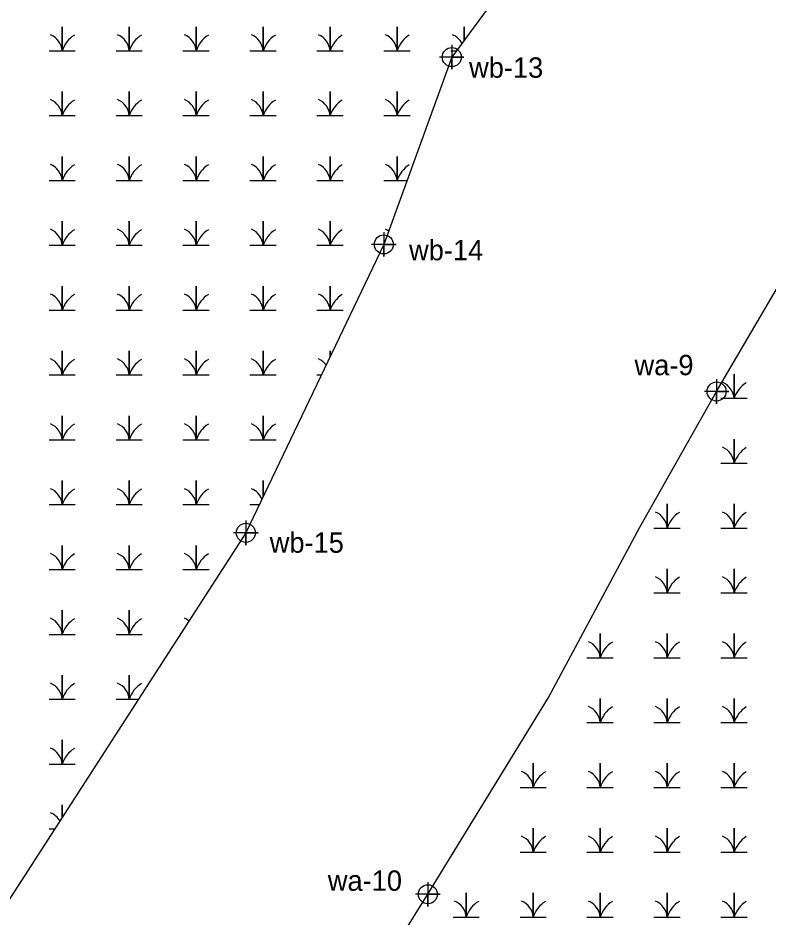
# Model space of a CAD drawing. Extents: x 2379288 to 2381905, y 330670 to 333511.
# Drawn here: x 2379849.1 to 2380033.3, y 331532.1 to 331753.1 of the extents above; entities that cross this region are included whole.
import ezdxf

# ---------------------------------------------------------------- set-up
doc = ezdxf.new("R2010")
doc.units = 0
for name, color, linetype in [('Exist Environmental Wetland Boundary', 7, 'Continuous'), ('Exist Environmental Wetland Boundary Cogo Number', 7, 'Continuous'), ('Exist Environmental Wetland Boundary Cogo Point CELL', 7, 'Continuous'), ('Exist Hydro Swamp or Marsh', 7, 'Continuous')]:
    doc.layers.add(name, color=color, linetype=linetype)

msp = doc.modelspace()

# ---------------------------------------------------------------- linework, layer by layer
at = {"layer": 'Exist Environmental Wetland Boundary'}
for points in [[(2380130.29, 332029.9), (2380102.32, 331972.59), (2380055.88, 331898.56), (2380034.74, 331855.71), (2379997.28, 331799.99), (2379955.67, 331743.45), (2379938.98, 331697.47), (2379905.07, 331626.66), (2379844.93, 331533.46), (2379815.25, 331542.18), (2379791.29, 331555.41), (2379761.99, 331575.7), (2379733.64, 331601.14), (2379721.48, 331609.71)], [(2379969.53, 331242.58), (2379951.18, 331271.07), (2379927.68, 331301.39), (2379890.44, 331365.66), (2379892.64, 331447.19), (2379906.39, 331470.26), (2379921.41, 331493.05), (2379928.27, 331503.45), (2379949.79, 331537.93), (2379979.44, 331586.24), (2380001.81, 331628.04), (2380020.7, 331661.36), (2380049.79, 331711.02), (2380074.34, 331755.11), (2380080.4, 331764.13), (2380105.64, 331802.62), (2380125.36, 331845.41), (2380131.51, 331853.8), (2380135.55, 331859.31), (2380151.44, 331880.98), (2380179.52, 331921.73), (2380190.43, 331937.74), (2380215.91, 331979.8)]]:
    msp.add_lwpolyline(points, dxfattribs=at)
at = {"layer": 'Exist Environmental Wetland Boundary Cogo Point CELL'}
for points in [[(2379955.66, 331746.45), (2379955.66, 331740.45), (2379955.66, 331743.45), (2379958.66, 331743.45), (2379952.66, 331743.45)], [(2379938.98, 331700.47), (2379938.98, 331694.47), (2379938.98, 331697.47), (2379941.98, 331697.47), (2379935.98, 331697.47)], [(2380020.7, 331664.36), (2380020.7, 331658.36), (2380020.7, 331661.36), (2380023.7, 331661.36), (2380017.7, 331661.36)], [(2379905.07, 331629.66), (2379905.07, 331623.66), (2379905.07, 331626.66), (2379908.07, 331626.66), (2379902.07, 331626.66)], [(2379949.79, 331540.93), (2379949.79, 331534.93), (2379949.79, 331537.93), (2379952.79, 331537.93), (2379946.79, 331537.93)]]:
    msp.add_lwpolyline(points, dxfattribs=at)
for centre in [(2379955.66, 331743.45), (2379938.98, 331697.47), (2380020.7, 331661.36), (2379905.07, 331626.66), (2379949.79, 331537.93)]:
    msp.add_circle(centre, 2.34, dxfattribs=at)
at = {"layer": 'Exist Hydro Swamp or Marsh'}
for p, q in [((2379955.45, 331745), (2379956.81, 331745)), ((2379922.54, 331665.41), (2379923.63, 331665.41)), ((2379906.09, 331633.58), (2379908.39, 331633.58)), ((2379856.74, 331553.99), (2379858.18, 331553.99))]:
    msp.add_line(p, q, dxfattribs=at)
for points in [[(2379856.74, 331745), (2379859.96, 331745), (2379859.96, 331750.92), (2379859.96, 331745), (2379863.19, 331745)], [(2379873.19, 331745), (2379876.42, 331745), (2379876.42, 331750.92), (2379876.42, 331745), (2379879.64, 331745)], [(2379889.64, 331745), (2379892.87, 331745), (2379892.87, 331750.92), (2379892.87, 331745), (2379896.09, 331745)], [(2379906.09, 331745), (2379909.32, 331745), (2379909.32, 331750.92), (2379909.32, 331745), (2379912.54, 331745)], [(2379922.54, 331745), (2379925.77, 331745), (2379925.77, 331750.92), (2379925.77, 331745), (2379928.99, 331745)], [(2379938.99, 331745), (2379942.22, 331745), (2379942.22, 331750.92), (2379942.22, 331745), (2379945.45, 331745)], [(2379958.67, 331747.53), (2379958.67, 331750.92), (2379958.67, 331747.53)], [(2379856.74, 331729.08), (2379859.96, 331729.08), (2379859.96, 331735), (2379859.96, 331729.08), (2379863.19, 331729.08)], [(2379873.19, 331729.08), (2379876.42, 331729.08), (2379876.42, 331735), (2379876.42, 331729.08), (2379879.64, 331729.08)], [(2379889.64, 331729.08), (2379892.87, 331729.08), (2379892.87, 331735), (2379892.87, 331729.08), (2379896.09, 331729.08)], [(2379906.09, 331729.08), (2379909.32, 331729.08), (2379909.32, 331735), (2379909.32, 331729.08), (2379912.54, 331729.08)], [(2379922.54, 331729.08), (2379925.77, 331729.08), (2379925.77, 331735), (2379925.77, 331729.08), (2379928.99, 331729.08)], [(2379938.99, 331729.08), (2379942.22, 331729.08), (2379942.22, 331735), (2379942.22, 331729.08), (2379945.45, 331729.08)], [(2379856.74, 331713.16), (2379859.96, 331713.16), (2379859.96, 331719.08), (2379859.96, 331713.16), (2379863.19, 331713.16)], [(2379873.19, 331713.16), (2379876.42, 331713.16), (2379876.42, 331719.08), (2379876.42, 331713.16), (2379879.64, 331713.16)], [(2379889.64, 331713.16), (2379892.87, 331713.16), (2379892.87, 331719.08), (2379892.87, 331713.16), (2379896.09, 331713.16)], [(2379906.09, 331713.16), (2379909.32, 331713.16), (2379909.32, 331719.08), (2379909.32, 331713.16), (2379912.54, 331713.16)], [(2379922.54, 331713.16), (2379925.77, 331713.16), (2379925.77, 331719.08), (2379925.77, 331713.16), (2379928.99, 331713.16)], [(2379938.99, 331713.16), (2379942.22, 331713.16), (2379942.22, 331719.08), (2379942.22, 331713.16), (2379944.68, 331713.16)], [(2379856.74, 331697.25), (2379859.96, 331697.25), (2379859.96, 331703.16), (2379859.96, 331697.25), (2379863.19, 331697.25)], [(2379873.19, 331697.25), (2379876.42, 331697.25), (2379876.42, 331703.16), (2379876.42, 331697.25), (2379879.64, 331697.25)], [(2379889.64, 331697.25), (2379892.87, 331697.25), (2379892.87, 331703.16), (2379892.87, 331697.25), (2379896.09, 331697.25)], [(2379906.09, 331697.25), (2379909.32, 331697.25), (2379909.32, 331703.16), (2379909.32, 331697.25), (2379912.54, 331697.25)], [(2379922.54, 331697.25), (2379925.77, 331697.25), (2379925.77, 331703.16), (2379925.77, 331697.25), (2379928.99, 331697.25)], [(2379856.74, 331681.33), (2379859.96, 331681.33), (2379859.96, 331687.25), (2379859.96, 331681.33), (2379863.19, 331681.33)], [(2379873.19, 331681.33), (2379876.42, 331681.33), (2379876.42, 331687.25), (2379876.42, 331681.33), (2379879.64, 331681.33)], [(2379889.64, 331681.33), (2379892.87, 331681.33), (2379892.87, 331687.25), (2379892.87, 331681.33), (2379896.09, 331681.33)], [(2379906.09, 331681.33), (2379909.32, 331681.33), (2379909.32, 331687.25), (2379909.32, 331681.33), (2379912.54, 331681.33)], [(2379922.54, 331681.33), (2379925.77, 331681.33), (2379925.77, 331687.25), (2379925.77, 331681.33), (2379928.99, 331681.33)], [(2379856.74, 331665.41), (2379859.96, 331665.41), (2379859.96, 331671.33), (2379859.96, 331665.41), (2379863.19, 331665.41)], [(2379873.19, 331665.41), (2379876.42, 331665.41), (2379876.42, 331671.33), (2379876.42, 331665.41), (2379879.64, 331665.41)], [(2379889.64, 331665.41), (2379892.87, 331665.41), (2379892.87, 331671.33), (2379892.87, 331665.41), (2379896.09, 331665.41)], [(2379906.09, 331665.41), (2379909.32, 331665.41), (2379909.32, 331671.33), (2379909.32, 331665.41), (2379912.54, 331665.41)], [(2379925.77, 331669.87), (2379925.77, 331671.33), (2379925.77, 331669.87)], [(2380021.78, 331659.68), (2380025, 331659.68), (2380025, 331665.6), (2380025, 331659.68), (2380028.23, 331659.68)], [(2379856.74, 331649.49), (2379859.96, 331649.49), (2379859.96, 331655.41), (2379859.96, 331649.49), (2379863.19, 331649.49)], [(2379873.19, 331649.49), (2379876.42, 331649.49), (2379876.42, 331655.41), (2379876.42, 331649.49), (2379879.64, 331649.49)], [(2379889.64, 331649.49), (2379892.87, 331649.49), (2379892.87, 331655.41), (2379892.87, 331649.49), (2379896.09, 331649.49)], [(2379906.09, 331649.49), (2379909.32, 331649.49), (2379909.32, 331655.41), (2379909.32, 331649.49), (2379912.54, 331649.49)], [(2380021.78, 331643.76), (2380025, 331643.76), (2380025, 331649.68), (2380025, 331643.76), (2380028.23, 331643.76)], [(2379856.74, 331633.58), (2379859.96, 331633.58), (2379859.96, 331639.49), (2379859.96, 331633.58), (2379863.19, 331633.58)], [(2379873.19, 331633.58), (2379876.42, 331633.58), (2379876.42, 331639.49), (2379876.42, 331633.58), (2379879.64, 331633.58)], [(2379889.64, 331633.58), (2379892.87, 331633.58), (2379892.87, 331639.49), (2379892.87, 331633.58), (2379896.09, 331633.58)], [(2379909.32, 331635.52), (2379909.32, 331639.49), (2379909.32, 331635.52)], [(2380005.32, 331627.84), (2380008.55, 331627.84), (2380008.55, 331633.76), (2380008.55, 331627.84), (2380011.78, 331627.84)], [(2380021.78, 331627.84), (2380025, 331627.84), (2380025, 331633.76), (2380025, 331627.84), (2380028.23, 331627.84)], [(2379856.74, 331617.66), (2379859.96, 331617.66), (2379859.96, 331623.58), (2379859.96, 331617.66), (2379863.19, 331617.66)], [(2379873.19, 331617.66), (2379876.42, 331617.66), (2379876.42, 331623.58), (2379876.42, 331617.66), (2379879.64, 331617.66)], [(2379889.64, 331617.66), (2379892.87, 331617.66), (2379892.87, 331623.58), (2379892.87, 331617.66), (2379896.09, 331617.66)], [(2380005.32, 331611.93), (2380008.55, 331611.93), (2380008.55, 331617.84), (2380008.55, 331611.93), (2380011.78, 331611.93)], [(2380021.78, 331611.93), (2380025, 331611.93), (2380025, 331617.84), (2380025, 331611.93), (2380028.23, 331611.93)], [(2379856.74, 331601.74), (2379859.96, 331601.74), (2379859.96, 331607.66), (2379859.96, 331601.74), (2379863.19, 331601.74)], [(2379873.19, 331601.74), (2379876.42, 331601.74), (2379876.42, 331607.66), (2379876.42, 331601.74), (2379879.64, 331601.74)], [(2379988.87, 331596.01), (2379992.1, 331596.01), (2379992.1, 331601.93), (2379992.1, 331596.01), (2379995.32, 331596.01)], [(2380005.32, 331596.01), (2380008.55, 331596.01), (2380008.55, 331601.93), (2380008.55, 331596.01), (2380011.78, 331596.01)], [(2380021.78, 331596.01), (2380025, 331596.01), (2380025, 331601.93), (2380025, 331596.01), (2380028.23, 331596.01)], [(2379856.74, 331585.82), (2379859.96, 331585.82), (2379859.96, 331591.74), (2379859.96, 331585.82), (2379863.19, 331585.82)], [(2379873.19, 331585.82), (2379876.42, 331585.82), (2379876.42, 331591.74), (2379876.42, 331585.82), (2379878.72, 331585.82)], [(2379988.87, 331580.09), (2379992.1, 331580.09), (2379992.1, 331586.01), (2379992.1, 331580.09), (2379995.32, 331580.09)], [(2380005.32, 331580.09), (2380008.55, 331580.09), (2380008.55, 331586.01), (2380008.55, 331580.09), (2380011.78, 331580.09)], [(2380021.78, 331580.09), (2380025, 331580.09), (2380025, 331586.01), (2380025, 331580.09), (2380028.23, 331580.09)], [(2379856.74, 331569.9), (2379859.96, 331569.9), (2379859.96, 331575.82), (2379859.96, 331569.9), (2379863.19, 331569.9)], [(2379972.42, 331564.17), (2379975.65, 331564.17), (2379975.65, 331570.09), (2379975.65, 331564.17), (2379978.87, 331564.17)], [(2379988.87, 331564.17), (2379992.1, 331564.17), (2379992.1, 331570.09), (2379992.1, 331564.17), (2379995.32, 331564.17)], [(2380005.32, 331564.17), (2380008.55, 331564.17), (2380008.55, 331570.09), (2380008.55, 331564.17), (2380011.78, 331564.17)], [(2380021.78, 331564.17), (2380025, 331564.17), (2380025, 331570.09), (2380025, 331564.17), (2380028.23, 331564.17)], [(2379859.96, 331556.75), (2379859.96, 331559.9), (2379859.96, 331556.75)], [(2379972.42, 331548.26), (2379975.65, 331548.26), (2379975.65, 331554.17), (2379975.65, 331548.26), (2379978.87, 331548.26)], [(2379988.87, 331548.26), (2379992.1, 331548.26), (2379992.1, 331554.17), (2379992.1, 331548.26), (2379995.32, 331548.26)], [(2380005.32, 331548.26), (2380008.55, 331548.26), (2380008.55, 331554.17), (2380008.55, 331548.26), (2380011.78, 331548.26)], [(2380021.78, 331548.26), (2380025, 331548.26), (2380025, 331554.17), (2380025, 331548.26), (2380028.23, 331548.26)], [(2379955.97, 331532.34), (2379959.2, 331532.34), (2379959.2, 331538.26), (2379959.2, 331532.34), (2379962.42, 331532.34)], [(2379972.42, 331532.34), (2379975.65, 331532.34), (2379975.65, 331538.26), (2379975.65, 331532.34), (2379978.87, 331532.34)], [(2379988.87, 331532.34), (2379992.1, 331532.34), (2379992.1, 331538.26), (2379992.1, 331532.34), (2379995.32, 331532.34)], [(2380005.32, 331532.34), (2380008.55, 331532.34), (2380008.55, 331538.26), (2380008.55, 331532.34), (2380011.78, 331532.34)], [(2380021.78, 331532.34), (2380025, 331532.34), (2380025, 331538.26), (2380025, 331532.34), (2380028.23, 331532.34)]]:
    msp.add_lwpolyline(points, dxfattribs=at)
for centre, radius, start, end in [((2379855.36, 331744.67), 4.61, 4.1403, 67.535), ((2379866.81, 331742.73), 7.21, 122.1274, 161.6222), ((2379871.82, 331744.67), 4.61, 4.1403, 67.535), ((2379883.26, 331742.73), 7.21, 122.1274, 161.6222), ((2379888.27, 331744.67), 4.61, 4.1403, 67.535), ((2379899.71, 331742.73), 7.21, 122.1274, 161.6222), ((2379904.72, 331744.67), 4.61, 4.1403, 67.535), ((2379916.16, 331742.73), 7.21, 122.1274, 161.6222), ((2379921.17, 331744.67), 4.61, 4.1403, 67.535), ((2379932.61, 331742.73), 7.21, 122.1274, 161.6222), ((2379937.62, 331744.67), 4.61, 4.1403, 67.535), ((2379949.06, 331742.73), 7.21, 122.1274, 161.6222), ((2379954.07, 331744.67), 4.61, 27.8897, 67.535), ((2379855.36, 331728.75), 4.61, 4.1403, 67.535), ((2379866.81, 331726.81), 7.21, 122.1274, 161.6222), ((2379871.82, 331728.75), 4.61, 4.1403, 67.535), ((2379883.26, 331726.81), 7.21, 122.1274, 161.6222), ((2379888.27, 331728.75), 4.61, 4.1403, 67.535), ((2379899.71, 331726.81), 7.21, 122.1274, 161.6222), ((2379904.72, 331728.75), 4.61, 4.1403, 67.535), ((2379916.16, 331726.81), 7.21, 122.1274, 161.6222), ((2379921.17, 331728.75), 4.61, 4.1403, 67.535), ((2379932.61, 331726.81), 7.21, 122.1274, 161.6222), ((2379937.62, 331728.75), 4.61, 4.1403, 67.535), ((2379949.06, 331726.81), 7.21, 122.1274, 161.6222), ((2379855.36, 331712.83), 4.61, 4.1403, 67.535), ((2379866.81, 331710.89), 7.21, 122.1274, 161.6222), ((2379871.82, 331712.83), 4.61, 4.1403, 67.535), ((2379883.26, 331710.89), 7.21, 122.1274, 161.6222), ((2379888.27, 331712.83), 4.61, 4.1403, 67.535), ((2379899.71, 331710.89), 7.21, 122.1274, 161.6222), ((2379904.72, 331712.83), 4.61, 4.1403, 67.535), ((2379916.16, 331710.89), 7.21, 122.1274, 161.6222), ((2379921.17, 331712.83), 4.61, 4.1403, 67.535), ((2379932.61, 331710.89), 7.21, 122.1274, 161.6222), ((2379937.62, 331712.83), 4.61, 4.1403, 67.535), ((2379949.06, 331710.89), 7.21, 122.1274, 161.6222), ((2379855.36, 331696.91), 4.61, 4.1403, 67.535), ((2379871.82, 331696.91), 4.61, 4.1403, 67.535), ((2379888.27, 331696.91), 4.61, 4.1403, 67.535), ((2379904.72, 331696.91), 4.61, 4.1403, 67.535), ((2379921.17, 331696.91), 4.61, 4.1403, 67.535), ((2379937.62, 331696.91), 4.61, 56.3559, 67.535), ((2379866.81, 331694.97), 7.21, 122.1274, 161.6222), ((2379883.26, 331694.97), 7.21, 122.1274, 161.6222), ((2379899.71, 331694.97), 7.21, 122.1274, 161.6222), ((2379916.16, 331694.97), 7.21, 122.1274, 161.6222), ((2379932.61, 331694.97), 7.21, 122.1274, 161.6222), ((2379855.36, 331681), 4.61, 4.1403, 67.535), ((2379866.81, 331679.06), 7.21, 122.1274, 161.6222), ((2379871.82, 331681), 4.61, 4.1403, 67.535), ((2379883.26, 331679.06), 7.21, 122.1274, 161.6222), ((2379888.27, 331681), 4.61, 4.1403, 67.535), ((2379899.71, 331679.06), 7.21, 122.1274, 161.6222), ((2379904.72, 331681), 4.61, 4.1403, 67.535), ((2379916.16, 331679.06), 7.21, 122.1274, 161.6222), ((2379921.17, 331681), 4.61, 4.1403, 67.535), ((2379932.61, 331679.06), 7.21, 122.1274, 161.6222), ((2379855.36, 331665.08), 4.61, 4.1403, 67.535), ((2379866.81, 331663.14), 7.21, 122.1274, 161.6222), ((2379871.82, 331665.08), 4.61, 4.1403, 67.535), ((2379883.26, 331663.14), 7.21, 122.1274, 161.6222), ((2379888.27, 331665.08), 4.61, 4.1403, 67.535), ((2379899.71, 331663.14), 7.21, 122.1274, 161.6222), ((2379904.72, 331665.08), 4.61, 4.1403, 67.535), ((2379916.16, 331663.14), 7.21, 122.1274, 161.6222), ((2379921.17, 331665.08), 4.61, 37.6311, 67.535), ((2380020.4, 331659.35), 4.61, 4.1403, 67.535), ((2380031.84, 331657.41), 7.21, 122.1274, 161.6222), ((2379855.36, 331649.16), 4.61, 4.1403, 67.535), ((2379866.81, 331647.22), 7.21, 122.1274, 161.6222), ((2379871.82, 331649.16), 4.61, 4.1403, 67.535), ((2379883.26, 331647.22), 7.21, 122.1274, 161.6222), ((2379888.27, 331649.16), 4.61, 4.1403, 67.535), ((2379899.71, 331647.22), 7.21, 122.1274, 161.6222), ((2379904.72, 331649.16), 4.61, 4.1403, 67.535), ((2379916.16, 331647.22), 7.21, 122.1274, 161.6222), ((2380020.4, 331643.43), 4.61, 4.1403, 67.535), ((2380031.84, 331641.49), 7.21, 122.1274, 161.6222), ((2379855.36, 331633.24), 4.61, 4.1403, 67.535), ((2379866.81, 331631.3), 7.21, 122.1274, 161.6222), ((2379871.82, 331633.24), 4.61, 4.1403, 67.535), ((2379883.26, 331631.3), 7.21, 122.1274, 161.6222), ((2379888.27, 331633.24), 4.61, 4.1403, 67.535), ((2379899.71, 331631.3), 7.21, 122.1274, 161.6222), ((2379904.72, 331633.24), 4.61, 21.0612, 67.535), ((2380003.95, 331627.51), 4.61, 4.1403, 67.535), ((2380015.39, 331625.57), 7.21, 122.1274, 161.6222), ((2380020.4, 331627.51), 4.61, 4.1403, 67.535), ((2380031.84, 331625.57), 7.21, 122.1274, 161.6222), ((2379855.36, 331617.32), 4.61, 4.1403, 67.535), ((2379871.82, 331617.32), 4.61, 4.1403, 67.535), ((2379888.27, 331617.32), 4.61, 4.1403, 67.535), ((2379866.81, 331615.38), 7.21, 122.1274, 161.6222), ((2379883.26, 331615.38), 7.21, 122.1274, 161.6222), ((2379899.71, 331615.38), 7.21, 122.1274, 161.6222), ((2380003.95, 331611.59), 4.61, 4.1403, 67.535), ((2380015.39, 331609.65), 7.21, 122.1274, 161.6222), ((2380020.4, 331611.59), 4.61, 4.1403, 67.535), ((2380031.84, 331609.65), 7.21, 122.1274, 161.6222), ((2379855.36, 331601.41), 4.61, 4.1403, 67.535), ((2379866.81, 331599.47), 7.21, 122.1274, 161.6222), ((2379871.82, 331601.41), 4.61, 4.1403, 67.535), ((2379883.26, 331599.47), 7.21, 122.1274, 161.6222), ((2379888.27, 331601.41), 4.61, 51.7956, 67.535), ((2379987.5, 331595.68), 4.61, 4.1403, 67.535), ((2379998.94, 331593.74), 7.21, 122.1274, 161.6222), ((2380003.95, 331595.68), 4.61, 4.1403, 67.535), ((2380015.39, 331593.74), 7.21, 122.1274, 161.6222), ((2380020.4, 331595.68), 4.61, 4.1403, 67.535), ((2380031.84, 331593.74), 7.21, 122.1274, 161.6222), ((2379855.36, 331585.49), 4.61, 4.1403, 67.535), ((2379866.81, 331583.55), 7.21, 122.1274, 161.6222), ((2379871.82, 331585.49), 4.61, 4.1403, 67.535), ((2379883.26, 331583.55), 7.21, 122.1274, 161.6222), ((2379987.5, 331579.76), 4.61, 4.1403, 67.535), ((2380003.95, 331579.76), 4.61, 4.1403, 67.535), ((2380020.4, 331579.76), 4.61, 4.1403, 67.535), ((2379998.94, 331577.82), 7.21, 122.1274, 161.6222), ((2380015.39, 331577.82), 7.21, 122.1274, 161.6222), ((2380031.84, 331577.82), 7.21, 122.1274, 161.6222), ((2379855.36, 331569.57), 4.61, 4.1403, 67.535), ((2379866.81, 331567.63), 7.21, 122.1274, 161.6222), ((2379971.05, 331563.84), 4.61, 4.1403, 67.535), ((2379982.49, 331561.9), 7.21, 122.1274, 161.6222), ((2379987.5, 331563.84), 4.61, 4.1403, 67.535), ((2379998.94, 331561.9), 7.21, 122.1274, 161.6222), ((2380003.95, 331563.84), 4.61, 4.1403, 67.535), ((2380015.39, 331561.9), 7.21, 122.1274, 161.6222), ((2380020.4, 331563.84), 4.61, 4.1403, 67.535), ((2380031.84, 331561.9), 7.21, 122.1274, 161.6222), ((2379855.36, 331553.65), 4.61, 28.886, 67.535), ((2379971.05, 331547.92), 4.61, 4.1403, 67.535), ((2379982.49, 331545.98), 7.21, 122.1274, 161.6222), ((2379987.5, 331547.92), 4.61, 4.1403, 67.535), ((2379998.94, 331545.98), 7.21, 122.1274, 161.6222), ((2380003.95, 331547.92), 4.61, 4.1403, 67.535), ((2380015.39, 331545.98), 7.21, 122.1274, 161.6222), ((2380020.4, 331547.92), 4.61, 4.1403, 67.535), ((2380031.84, 331545.98), 7.21, 122.1274, 161.6222), ((2379954.6, 331532.01), 4.61, 4.1403, 67.535), ((2379966.04, 331530.07), 7.21, 122.1274, 161.6222), ((2379971.05, 331532.01), 4.61, 4.1403, 67.535), ((2379982.49, 331530.07), 7.21, 122.1274, 161.6222), ((2379987.5, 331532.01), 4.61, 4.1403, 67.535), ((2379998.94, 331530.07), 7.21, 122.1274, 161.6222), ((2380003.95, 331532.01), 4.61, 4.1403, 67.535), ((2380015.39, 331530.07), 7.21, 122.1274, 161.6222), ((2380020.4, 331532.01), 4.61, 4.1403, 67.535), ((2380031.84, 331530.07), 7.21, 122.1274, 161.6222)]:
    msp.add_arc(centre, radius, start, end, dxfattribs=at)

# ---------------------------------------------------------------- texts
at = {"layer": 'Exist Environmental Wetland Boundary Cogo Number'}
for s, p in [('wb-13', (2379959.91, 331738.38)), ('wb-14', (2379945.17, 331693.57)), ('wa-9', (2380000.55, 331665.35)), ('wb-15', (2379910.95, 331621.77)), ('wa-10', (2379925.22, 331538.78))]:
    msp.add_text(s, height=5, dxfattribs=at).set_placement(p)

doc.saveas('drawing.dxf')
